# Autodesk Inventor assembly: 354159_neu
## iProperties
Company: Mayer & Müller AG Schaltgeräte
Created: 2006-10
Part Number: 354159_neu
Document SubType Name: Assembly
Designer: Natti_01
Description: Hebel kpl.
Mass: 332.764 g
Surface Area: 224.075 cm^2
Volume: 42.4444 cm^3
Density: 7.84 g/cm^3
Author: Natti_01
